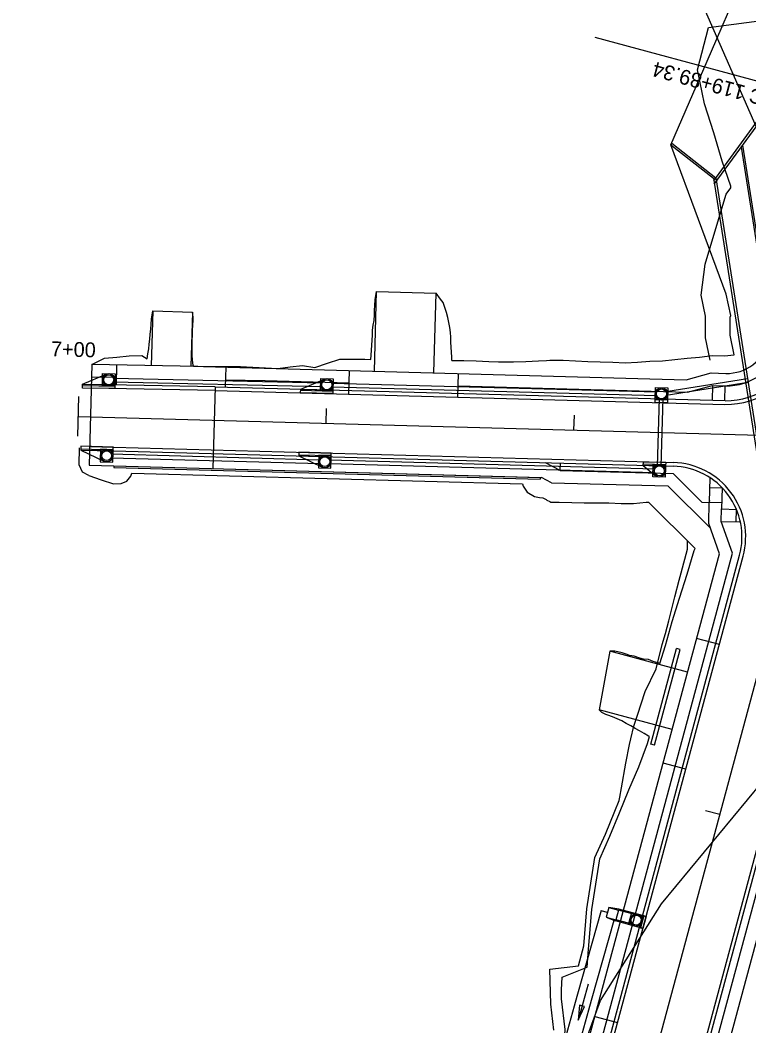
# Model space of a CAD drawing. Extents: x 979959 to 994833, y 1835619 to 1845316.
# Drawn here: x 992409.6 to 992703.6, y 1840438.2 to 1840843.7 of the extents above; entities that cross this region are included whole.
import ezdxf

# ---------------------------------------------------------------- set-up
doc = ezdxf.new("R2010")
doc.units = 0
for name, color, linetype in [('43', 7, 'Continuous'), ('Concrete Walk Type Special', 7, 'Continuous'), ('Future 5 Lane Construction Limits', 7, 'Continuous'), ('R_Drainage', 7, 'Continuous'), ('R_Drainage Structure', 7, 'Continuous'), ('R_Horz Alg', 7, 'Continuous'), ('R_Horz Alg Annot', 7, 'Continuous'), ('R_Horz Alg Stationing', 7, 'Continuous'), ('R_Proposed Const Limits', 7, 'Continuous'), ('R_Proposed Road', 7, 'Continuous'), ('R_Special Ditch', 7, 'Continuous')]:
    doc.layers.add(name, color=color, linetype=linetype)

msp = doc.modelspace()

# ---------------------------------------------------------------- linework, layer by layer
at = {"layer": '43'}
msp.add_lwpolyline([(992621.79, 1840368.15), (992628.07, 1840405.79), (992643.68, 1840448.4), (992668.29, 1840487.44), (992720.39, 1840550.23), (992730.06, 1840577.03), (992737.54, 1840627.9), (992738.03, 1840675.61), (992735.39, 1840714.93), (992711.35, 1840789.79), (992657.1, 1840913.35), (992616.01, 1840968.75), (992554.37, 1841054.01), (992492.51, 1841112.85), (992422.69, 1841167.63), (992343.9, 1841218.47), (992195.05, 1841300.3), (992123.04, 1841334.73), (992016.5, 1841376.04), (991968.17, 1841403.44), (991911.14, 1841449.18)], dxfattribs=at)
at = {"layer": 'Concrete Walk Type Special'}
for p, q in [((992447.42, 1840663.96), (992447.41, 1840663.3)), ((992447.41, 1840663.3), (992619.34, 1840658.6)), ((992447.42, 1840663.96), (992619.36, 1840659.27)), ((992619.36, 1840659.27), (992619.34, 1840658.6))]:
    msp.add_line(p, q, dxfattribs=at)
at = {"layer": 'Future 5 Lane Construction Limits'}
for points in [[(992687.9, 1840706.65), (992686, 1840715.67), (992686.07, 1840724.32), (992684.28, 1840732.82), (992685.95, 1840745.38), (992690.25, 1840759.7), (992694.37, 1840773.6), (992696.29, 1840776.06), (992696.29, 1840776.8), (992692.82, 1840786.86), (992689.39, 1840798.23), (992685.6, 1840810), (992682.82, 1840823.66), (992687.22, 1840840.75), (992712.85, 1840844.13)], [(992651.25, 1840529.1), (992651.5, 1840530.44), (992652.25, 1840534.16), (992653.87, 1840544.08), (992655.43, 1840551.69), (992655.9, 1840553.89), (992657.17, 1840559.03), (992658.62, 1840563.52), (992661.7, 1840573.04), (992666.17, 1840582.19), (992668.53, 1840591.92), (992669.97, 1840596.36), (992671.28, 1840601.53), (992673.72, 1840611.23), (992675.41, 1840617.86), (992676.22, 1840620.91), (992678.76, 1840630.46), (992678.79, 1840633.82)], [(992637.02, 1840470.52), (992638.21, 1840485.34), (992641.47, 1840506.05), (992645.68, 1840515.51), (992649.48, 1840524.81), (992651.25, 1840529.1)], [(992634.83, 1840462.41), (992637.02, 1840470.52)], [(992624.94, 1840436.39), (992624.94, 1840436.42), (992623.68, 1840446.93), (992623.26, 1840461.03), (992634.83, 1840462.41)]]:
    msp.add_lwpolyline(points, dxfattribs=at)
at = {"layer": 'R_Drainage'}
for p, q in [((992689.4, 1840778.98), (992722.23, 1840824.06)), ((992689.62, 1840777.58), (992722.44, 1840822.65)), ((992672.55, 1840794.05), (992672.09, 1840793.45)), ((992672.55, 1840794.05), (992690.27, 1840780.17)), ((992672.09, 1840793.45), (992689.24, 1840780.03)), ((992700.48, 1840792.49), (992744.77, 1840510.78)), ((992701.03, 1840793.26), (992745.33, 1840511.55)), ((992689.24, 1840780.01), (992734.13, 1840494.53)), ((992690.27, 1840780.17), (992734.78, 1840497.06)), ((992434.82, 1840696.87), (992444.37, 1840700.98)), ((992442.9, 1840701.22), (992447.9, 1840701.13)), ((992447.19, 1840697.89), (992531.48, 1840695.97)), ((992447.23, 1840699.39), (992531.51, 1840697.46)), ((992522.8, 1840694.96), (992532.38, 1840698.98)), ((992530.92, 1840699.24), (992535.92, 1840699.1)), ((992535.22, 1840697.37), (992666.47, 1840693.8)), ((992670.01, 1840694.03), (992703, 1840699.21)), ((992670.25, 1840692.55), (992703.23, 1840697.73)), ((992434.81, 1840696.37), (992447.81, 1840696.13)), ((992522.78, 1840694.46), (992535.78, 1840694.11)), ((992535.18, 1840695.87), (992666.43, 1840692.3)), ((992665.87, 1840695.57), (992670.87, 1840695.43)), ((992666.73, 1840663.88), (992667.5, 1840691.17)), ((992668.23, 1840663.83), (992669, 1840691.12)), ((992434.08, 1840670.38), (992443.43, 1840665.84)), ((992434.1, 1840670.88), (992447.09, 1840670.52)), ((992446.4, 1840668.79), (992530.67, 1840666.48)), ((992522.07, 1840668.47), (992535.07, 1840668.12)), ((992441.96, 1840665.66), (992446.96, 1840665.52)), ((992446.36, 1840667.29), (992530.63, 1840664.99)), ((992522.06, 1840667.97), (992531.41, 1840663.43)), ((992534.33, 1840664.88), (992665.55, 1840661.3)), ((992534.38, 1840666.38), (992665.59, 1840662.8)), ((992660.98, 1840664.18), (992665.81, 1840660.09)), ((992669.99, 1840664.43), (992661, 1840664.68)), ((992529.93, 1840663.25), (992534.93, 1840663.12)), ((992669.86, 1840659.43), (992664.86, 1840659.57)), ((992647.06, 1840485.85), (992646.02, 1840481.99)), ((992651.05, 1840485.3), (992647.06, 1840485.85)), ((992647.06, 1840485.85), (992650.92, 1840484.81)), ((992646.54, 1840483.92), (992643.99, 1840484.61)), ((992646.02, 1840481.99), (992649.75, 1840480.47)), ((992646.02, 1840481.99), (992649.88, 1840480.95)), ((992650.92, 1840484.81), (992649.88, 1840480.95)), ((992660.57, 1840482.22), (992650.92, 1840484.81)), ((992661.19, 1840482.57), (992651.05, 1840485.3)), ((992655.06, 1840479.04), (992656.36, 1840483.87)), ((992660.57, 1840482.22), (992659.53, 1840478.35)), ((992661.19, 1840482.57), (992659.89, 1840477.74)), ((992659.89, 1840477.74), (992649.75, 1840480.47)), ((992659.53, 1840478.35), (992649.88, 1840480.95)), ((992659.4, 1840477.87), (992660.85, 1840477.48))]:
    msp.add_line(p, q, dxfattribs=at)
for points in [[(992442.9, 1840701.22), (992447.9, 1840701.13), (992447.81, 1840696.13), (992442.81, 1840696.23)], [(992434.82, 1840696.87), (992447.82, 1840696.63), (992447.79, 1840695.13), (992434.79, 1840695.37)], [(992530.92, 1840699.24), (992535.92, 1840699.1), (992535.78, 1840694.11), (992530.78, 1840694.24)], [(992522.8, 1840694.96), (992535.79, 1840694.61), (992535.75, 1840693.11), (992522.76, 1840693.46)], [(992665.87, 1840695.57), (992670.87, 1840695.43), (992670.73, 1840690.43), (992665.73, 1840690.57)], [(992665.75, 1840691.07), (992670.74, 1840690.93), (992670.7, 1840689.43), (992665.7, 1840689.57)], [(992434.08, 1840670.38), (992447.08, 1840670.02), (992447.12, 1840671.52), (992434.12, 1840671.88)], [(992441.96, 1840665.66), (992446.96, 1840665.52), (992447.09, 1840670.52), (992442.09, 1840670.66)], [(992522.06, 1840667.97), (992535.06, 1840667.62), (992535.1, 1840669.11), (992522.1, 1840669.47)], [(992529.93, 1840663.25), (992534.93, 1840663.12), (992535.07, 1840668.12), (992530.07, 1840668.25)], [(992669.98, 1840663.93), (992660.98, 1840664.18), (992661.02, 1840665.68), (992670.02, 1840665.43)], [(992669.86, 1840659.43), (992664.86, 1840659.57), (992664.99, 1840664.57), (992669.99, 1840664.43)], [(992655.06, 1840479.04), (992656.36, 1840483.87), (992661.19, 1840482.57), (992659.89, 1840477.74)], [(992659.41, 1840477.87), (992660.7, 1840482.7), (992662.15, 1840482.31), (992660.85, 1840477.48)]]:
    msp.add_lwpolyline(points, close=True, dxfattribs=at)
for points in [[(992644, 1840484.65), (992634.47, 1840451.01), (992633.51, 1840447.61), (992633.1, 1840446.15), (992630.41, 1840436.51), (992629.57, 1840433.49)], [(992660.85, 1840477.48), (992662.15, 1840482.31), (992660.7, 1840482.7), (992659.4, 1840477.87)], [(992649.12, 1840480.73), (992640.24, 1840449.38), (992639.28, 1840445.99), (992638.87, 1840444.53), (992636.19, 1840434.9), (992635.35, 1840431.89)]]:
    msp.add_lwpolyline(points, dxfattribs=at)
for centre, radius in [((992445.36, 1840698.68), 2.5), ((992445.36, 1840698.68), 2.5), ((992445.36, 1840698.68), 2), ((992445.36, 1840698.68), 2), ((992533.35, 1840696.67), 2.5), ((992533.35, 1840696.67), 2.5), ((992533.35, 1840696.67), 2), ((992533.35, 1840696.67), 2), ((992668.3, 1840693), 2.5), ((992668.3, 1840693), 2.5), ((992668.3, 1840693), 2), ((992668.3, 1840693), 2), ((992444.53, 1840668.09), 2.5), ((992444.53, 1840668.09), 2.5), ((992444.53, 1840668.09), 2), ((992444.53, 1840668.09), 2), ((992532.5, 1840665.68), 2.5), ((992532.5, 1840665.68), 2.5), ((992532.5, 1840665.68), 2), ((992532.5, 1840665.68), 2), ((992667.43, 1840662), 2.5), ((992667.43, 1840662), 2.5), ((992667.43, 1840662), 2), ((992667.43, 1840662), 2), ((992658.12, 1840480.81), 2.5), ((992658.12, 1840480.81), 2.5), ((992658.12, 1840480.81), 2), ((992658.12, 1840480.81), 2)]:
    msp.add_circle(centre, radius, dxfattribs=at)
at = {"layer": 'R_Drainage Structure'}
for p, q in [((992664, 1840551.71), (992674.4, 1840590.33)), ((992665.45, 1840551.32), (992675.85, 1840589.94)), ((992675.85, 1840589.94), (992674.4, 1840590.33)), ((992665.45, 1840551.32), (992664, 1840551.71))]:
    msp.add_line(p, q, dxfattribs=at)
at = {"layer": 'R_Horz Alg'}
for p, q in [((992538.36, 1839953.12), (992767.08, 1840802.89)), ((992432.96, 1840683.91), (992732.85, 1840675.72))]:
    msp.add_line(p, q, dxfattribs=at)
at = {"layer": 'R_Horz Alg Annot'}
msp.add_lwpolyline([(992767.08, 1840802.89), (992641.55, 1840836.68)], dxfattribs=at)
at = {"layer": 'R_Horz Alg Stationing'}
for points in [[(992433.18, 1840691.91), (992432.74, 1840675.91)], [(992533.09, 1840687.18), (992532.93, 1840681.18)], [(992633.05, 1840684.45), (992632.89, 1840678.45)], [(992686.09, 1840525.06), (992691.88, 1840523.5)]]:
    msp.add_lwpolyline(points, dxfattribs=at)
at = {"layer": 'R_Proposed Const Limits'}
for p, q in [((992433.43, 1840664.39), (992433.62, 1840671.32)), ((992434.79, 1840661.39), (992433.43, 1840664.39)), ((992437.31, 1840660.12), (992434.79, 1840661.39)), ((992454.64, 1840661.1), (992612.29, 1840656.79)), ((992663.12, 1840649.34), (992681.94, 1840630.7))]:
    msp.add_line(p, q, dxfattribs=at)
for points in [[(992688.47, 1840831.21), (992699.7, 1840857.09), (992699.51, 1840860.91), (992699.25, 1840865.87), (992699.71, 1840874.44), (992699.63, 1840883.04), (992698.74, 1840891.7), (992698.42, 1840900.23), (992706.37, 1840908.06), (992710.06, 1840916.43), (992711.08, 1840925.02), (992712.01, 1840933.64), (992712.88, 1840942.28), (992713.78, 1840950.96), (992714.48, 1840959.66), (992714.96, 1840968.39), (992715.24, 1840977.14), (992715.66, 1840980.46)], [(992697.69, 1840708.7), (992696.01, 1840716.68), (992696.06, 1840723.94), (992696.23, 1840724.58), (992694.42, 1840733.2), (992672.09, 1840793.45), (992688.47, 1840831.21)], [(992552.52, 1840726.74), (992552.66, 1840728.66), (992552.79, 1840730.98), (992553.38, 1840734.26)], [(992583.8, 1840706.49), (992583.73, 1840707.8), (992583.62, 1840709.8), (992583.51, 1840711.81), (992583.4, 1840713.81), (992583.3, 1840715.82), (992583.15, 1840717.82), (992582.98, 1840719.83), (992582.6, 1840721.84), (992582.15, 1840723.85), (992581.61, 1840725.87), (992580.95, 1840727.88), (992580.3, 1840729.9), (992579.15, 1840731.25), (992577.37, 1840733.6)], [(992460.85, 1840707.2), (992461.13, 1840709.15), (992461.51, 1840711.14), (992461.72, 1840713.13), (992461.91, 1840715.13), (992462.09, 1840717.13), (992462.28, 1840719.12), (992462.47, 1840721.12), (992462.65, 1840723.11), (992462.7, 1840724.11), (992463.14, 1840726.47)], [(992479.48, 1840704.25), (992479.39, 1840704.65), (992479.16, 1840706.66), (992479.07, 1840708.66), (992479.03, 1840710.66), (992478.99, 1840712.66), (992479, 1840714.66), (992479.1, 1840716.66), (992479.2, 1840718.66), (992479.31, 1840720.66), (992479.4, 1840722.66), (992479.38, 1840723.99), (992479.13, 1840725.91)], [(992551.1, 1840706.88), (992551.21, 1840708.69), (992551.33, 1840710.69), (992551.45, 1840712.68), (992551.57, 1840714.68), (992551.69, 1840716.68), (992551.81, 1840718.68), (992552.01, 1840720.67), (992552.39, 1840722.66), (992552.5, 1840724.93), (992552.52, 1840726.74)], [(992583.8, 1840706.49), (992588.64, 1840706.46), (992593.63, 1840706.31), (992598.63, 1840706.11), (992602.63, 1840705.97), (992603.45, 1840705.94), (992603.63, 1840705.94), (992608.63, 1840705.89), (992613.64, 1840706.12), (992618.65, 1840706.4), (992621.99, 1840706.53), (992623.32, 1840706.58), (992623.65, 1840706.6), (992624.79, 1840706.65), (992625.24, 1840706.67), (992628.65, 1840706.56), (992633.65, 1840706.33), (992638.65, 1840706.11), (992643.64, 1840705.92), (992648.64, 1840705.74), (992653.64, 1840705.59), (992658.64, 1840705.8), (992663.66, 1840706.18), (992668.67, 1840706.41), (992673.68, 1840706.83), (992678.7, 1840707.4), (992683.71, 1840707.85), (992688.73, 1840708.5), (992693.73, 1840708.39), (992697.69, 1840708.7)], [(992438.54, 1840704.81), (992443.61, 1840707.45), (992448.62, 1840707.83), (992453.64, 1840708.33), (992458.64, 1840708.43), (992460.85, 1840707.2)], [(992528.54, 1840703.69), (992533.59, 1840705.35), (992538.63, 1840707.02), (992543.64, 1840707.04), (992548.64, 1840707), (992551.1, 1840706.88)], [(992479.48, 1840704.25), (992483.53, 1840704.05)], [(992483.53, 1840704.05), (992488.53, 1840704.04)], [(992488.53, 1840704.04), (992493.53, 1840704), (992498.54, 1840704.02), (992503.53, 1840703.8), (992508.53, 1840703.51), (992513.52, 1840703.24)], [(992513.52, 1840703.24), (992518.54, 1840703.96), (992523.56, 1840704.52), (992528.54, 1840703.69)], [(992437.31, 1840660.12), (992442.27, 1840658.37), (992447.23, 1840656.71), (992450.4, 1840656.88), (992452.71, 1840657.87), (992454.29, 1840659.85), (992454.64, 1840661.1)], [(992612.29, 1840656.79), (992612.52, 1840655.82), (992614.08, 1840653.44), (992617.03, 1840651.6), (992619.14, 1840651.24), (992620.47, 1840651.07), (992621.78, 1840650.37), (992622.11, 1840650.19), (992623.23, 1840649.59), (992623.67, 1840649.35), (992627.09, 1840649.32), (992632.09, 1840649.24), (992637.09, 1840649.15), (992642.09, 1840649.07), (992647.09, 1840649.1), (992652.09, 1840648.88), (992657.09, 1840648.76), (992662.11, 1840649.4), (992663.12, 1840649.34)], [(992667.62, 1840584.36), (992669.9, 1840591.55), (992672.61, 1840601.17), (992675.64, 1840610.71), (992678.64, 1840620.26), (992681.55, 1840629.83), (992681.94, 1840630.7)], [(992657.3, 1840587.28), (992655.4, 1840587.57), (992654.42, 1840587.98), (992652.52, 1840588.54), (992649.52, 1840589.26), (992647.46, 1840589.3)], [(992664.98, 1840585.16), (992663.12, 1840585.94), (992661.1, 1840586.11), (992659.24, 1840586.59), (992657.3, 1840587.28)], [(992667.62, 1840584.36), (992666.9, 1840584.58), (992664.98, 1840585.16)], [(992663.45, 1840554.83), (992663.09, 1840555.03), (992661.31, 1840556.11), (992659.5, 1840557.1), (992657.7, 1840558.09), (992655.9, 1840559.12), (992654.11, 1840560.16), (992652.32, 1840561.2), (992650.45, 1840561.96), (992648.59, 1840562.73), (992646.72, 1840563.5), (992645.82, 1840563.76), (992644.22, 1840564.6), (992643.22, 1840565.59)], [(992629.14, 1840431.95), (992629.43, 1840436.75), (992628, 1840449.06), (992628.03, 1840452.71), (992628.29, 1840457.77), (992638.27, 1840461.88), (992638.91, 1840469.13), (992640.19, 1840485.11), (992643.41, 1840505.48), (992647.52, 1840514.72), (992651.33, 1840524.05), (992655.17, 1840533.38), (992659.13, 1840542.67), (992662.71, 1840552.06), (992663.45, 1840554.83)]]:
    msp.add_lwpolyline(points, dxfattribs=at)
at = {"layer": 'R_Proposed Road'}
for p, q in [((992552.51, 1840702.15), (992553.38, 1840734.26)), ((992553.38, 1840734.26), (992577.37, 1840733.6)), ((992576.5, 1840701.5), (992577.37, 1840733.6)), ((992463.14, 1840726.47), (992462.53, 1840704.32)), ((992463.14, 1840726.47), (992479.13, 1840725.91)), ((992479.13, 1840725.91), (992478.53, 1840704.08)), ((992438.54, 1840704.81), (992437.43, 1840664.28)), ((992488.46, 1840703.9), (992438.54, 1840704.81)), ((992448.53, 1840704.62), (992448.32, 1840696.63)), ((992488.46, 1840703.9), (992488.53, 1840703.9)), ((992488.53, 1840703.9), (992678.22, 1840698.72)), ((992492.53, 1840703.79), (992492.31, 1840695.79)), ((992542.25, 1840692.93), (992542.51, 1840702.42)), ((992586.23, 1840691.73), (992586.49, 1840701.22)), ((992678.22, 1840698.72), (992688.3, 1840701.44)), ((992688.3, 1840701.44), (992694.25, 1840701.28)), ((992488.31, 1840695.9), (992438.32, 1840696.81)), ((992448.4, 1840699.63), (992438.44, 1840699.81)), ((992492.39, 1840698.69), (992508.37, 1840698.36)), ((992508.39, 1840698.35), (992542.37, 1840697.43)), ((992488.27, 1840694.4), (992438.28, 1840695.31)), ((992488.31, 1840695.9), (992487.41, 1840662.91)), ((992488.27, 1840694.4), (992693.91, 1840688.79)), ((992488.31, 1840695.9), (992693.95, 1840690.29)), ((992586.36, 1840696.23), (992678.82, 1840693.7)), ((992678.82, 1840693.7), (992688.9, 1840696.43)), ((992688.9, 1840696.43), (992694.12, 1840696.28)), ((992437.59, 1840670.28), (992673.06, 1840663.85)), ((992437.63, 1840671.78), (992673.1, 1840665.35)), ((992437.43, 1840664.28), (992619.94, 1840659.29)), ((992627.44, 1840662.09), (992621.52, 1840665.25)), ((992627.44, 1840662.09), (992627.52, 1840665.09)), ((992627.44, 1840662.09), (992672.98, 1840660.85)), ((992684.55, 1840649.38), (992672.98, 1840660.85)), ((992623.89, 1840657.19), (992619.94, 1840659.29)), ((992623.89, 1840657.19), (992670.86, 1840655.9)), ((992688.06, 1840638.87), (992670.86, 1840655.9)), ((992687.78, 1840655.3), (992692.77, 1840655.16)), ((992684.55, 1840649.38), (992692.61, 1840649.16)), ((992687.38, 1840640.81), (992687.61, 1840649.3)), ((992692.4, 1840641.61), (992692.54, 1840646.61)), ((992692.54, 1840646.61), (992698.53, 1840646.45)), ((992698.4, 1840641.45), (992698.53, 1840646.45)), ((992691.67, 1840628.54), (992687.38, 1840640.81)), ((992692.4, 1840641.61), (992700.13, 1840641.4)), ((992696.9, 1840628.73), (992692.4, 1840641.61)), ((992511.8, 1839960.26), (992691.67, 1840628.54)), ((992516.63, 1839958.96), (992696.9, 1840628.73)), ((992519.53, 1839958.18), (992699.8, 1840627.95)), ((992520.98, 1839957.79), (992701.25, 1840627.56)), ((992691.65, 1840591.91), (992682.48, 1840594.38)), ((992647.46, 1840589.3), (992643.22, 1840565.59)), ((992678.84, 1840580.86), (992647.46, 1840589.3)), ((992672.6, 1840557.68), (992643.22, 1840565.59)), ((992678.14, 1840541.69), (992668.96, 1840544.16)), ((992555.74, 1839948.44), (992713.43, 1840534.3)), ((992557.19, 1839948.05), (992714.88, 1840533.91)), ((992560.08, 1839947.27), (992717.77, 1840533.13)), ((992564.91, 1839945.97), (992722.6, 1840531.83)), ((992641.46, 1840441.98), (992650.63, 1840439.51))]:
    msp.add_line(p, q, dxfattribs=at)
for points in [[(992688.9, 1840696.43), (992688.74, 1840690.43)], [(992693.9, 1840696.29), (992693.73, 1840690.29)], [(992687.88, 1840659.21), (992687.61, 1840649.3)], [(992692.77, 1840655.16), (992692.54, 1840646.61)], [(992687.63, 1840650.01), (992687.61, 1840649.3)]]:
    msp.add_lwpolyline(points, dxfattribs=at)
for centre, radius, start, end in [((992240.16, 1840944.72), 523.17, 344.9354, 28.1934), ((992240.16, 1840944.72), 518.17, 344.9354, 28.1934), ((992694.73, 1840718.77), 22.5, 268.4354, 344.9354), ((992694.73, 1840718.77), 17.5, 268.4354, 344.9354), ((992694.73, 1840718.77), 30, 268.4354, 344.9354), ((992694.73, 1840718.77), 28.5, 268.4354, 344.9354), ((992672.28, 1840635.36), 30, 344.9354, 88.4354), ((992672.28, 1840635.36), 28.5, 344.9354, 88.4354)]:
    msp.add_arc(centre, radius, start, end, dxfattribs=at)
at = {"layer": 'R_Special Ditch'}
for p, q in [((992635.24, 1840446.59), (992634.64, 1840440.52)), ((992634.64, 1840440.52), (992637.27, 1840446.02)), ((992637.27, 1840446.02), (992635.24, 1840446.59))]:
    msp.add_line(p, q, dxfattribs=at)
msp.add_lwpolyline([(992638.7, 1840454.96), (992637.35, 1840450.2), (992636.4, 1840446.8), (992635.99, 1840445.34), (992634.64, 1840440.52)], dxfattribs=at)

# ---------------------------------------------------------------- texts
at = {"layer": 'R_Horz Alg Annot'}
msp.add_text('PC 119+89.34', height=6, rotation=164.9354, dxfattribs=at).set_placement((992715.48, 1840813.67))
at = {"layer": 'R_Horz Alg Stationing'}
msp.add_text('7+00', height=6, rotation=358.4354, dxfattribs=at).set_placement((992421.98, 1840708.22))

doc.saveas('drawing.dxf')
